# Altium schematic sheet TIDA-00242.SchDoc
size 431 x 279 mm; Date: Not shown in title block; ApprovedBy: Not shown in title block; CheckedBy: Not shown in title block; Author: Not shown in title block; CompanyName: Not shown in title block; Engineer: Not shown in title block; Organization: Not shown in title block; Address1: Not shown in title block; Address2: Not shown in title block; Address3: Not shown in title block; Address4: Not shown in title block; DocumentNumber: 1; Revision: Use project parameter SCH_Rev; SheetNumber: 2; SheetTotal: 3; PageSetup: Record=PageOptions|CenterHorizontal=True|CenterVertical=True|PrintScale=0.64|XCorrection=1.00|YCorrection=1.00|PrintKind=0|BorderSize=5000000|LeftOffset=0|BottomOffset=0|Orientation=2|PaperLength=1000|PaperWidth=1000|Scale=100|PaperSource=15|PrintQuality=600|MediaType=1|DitherType=10|PaperKind=Letter|PrintScaleMode=1
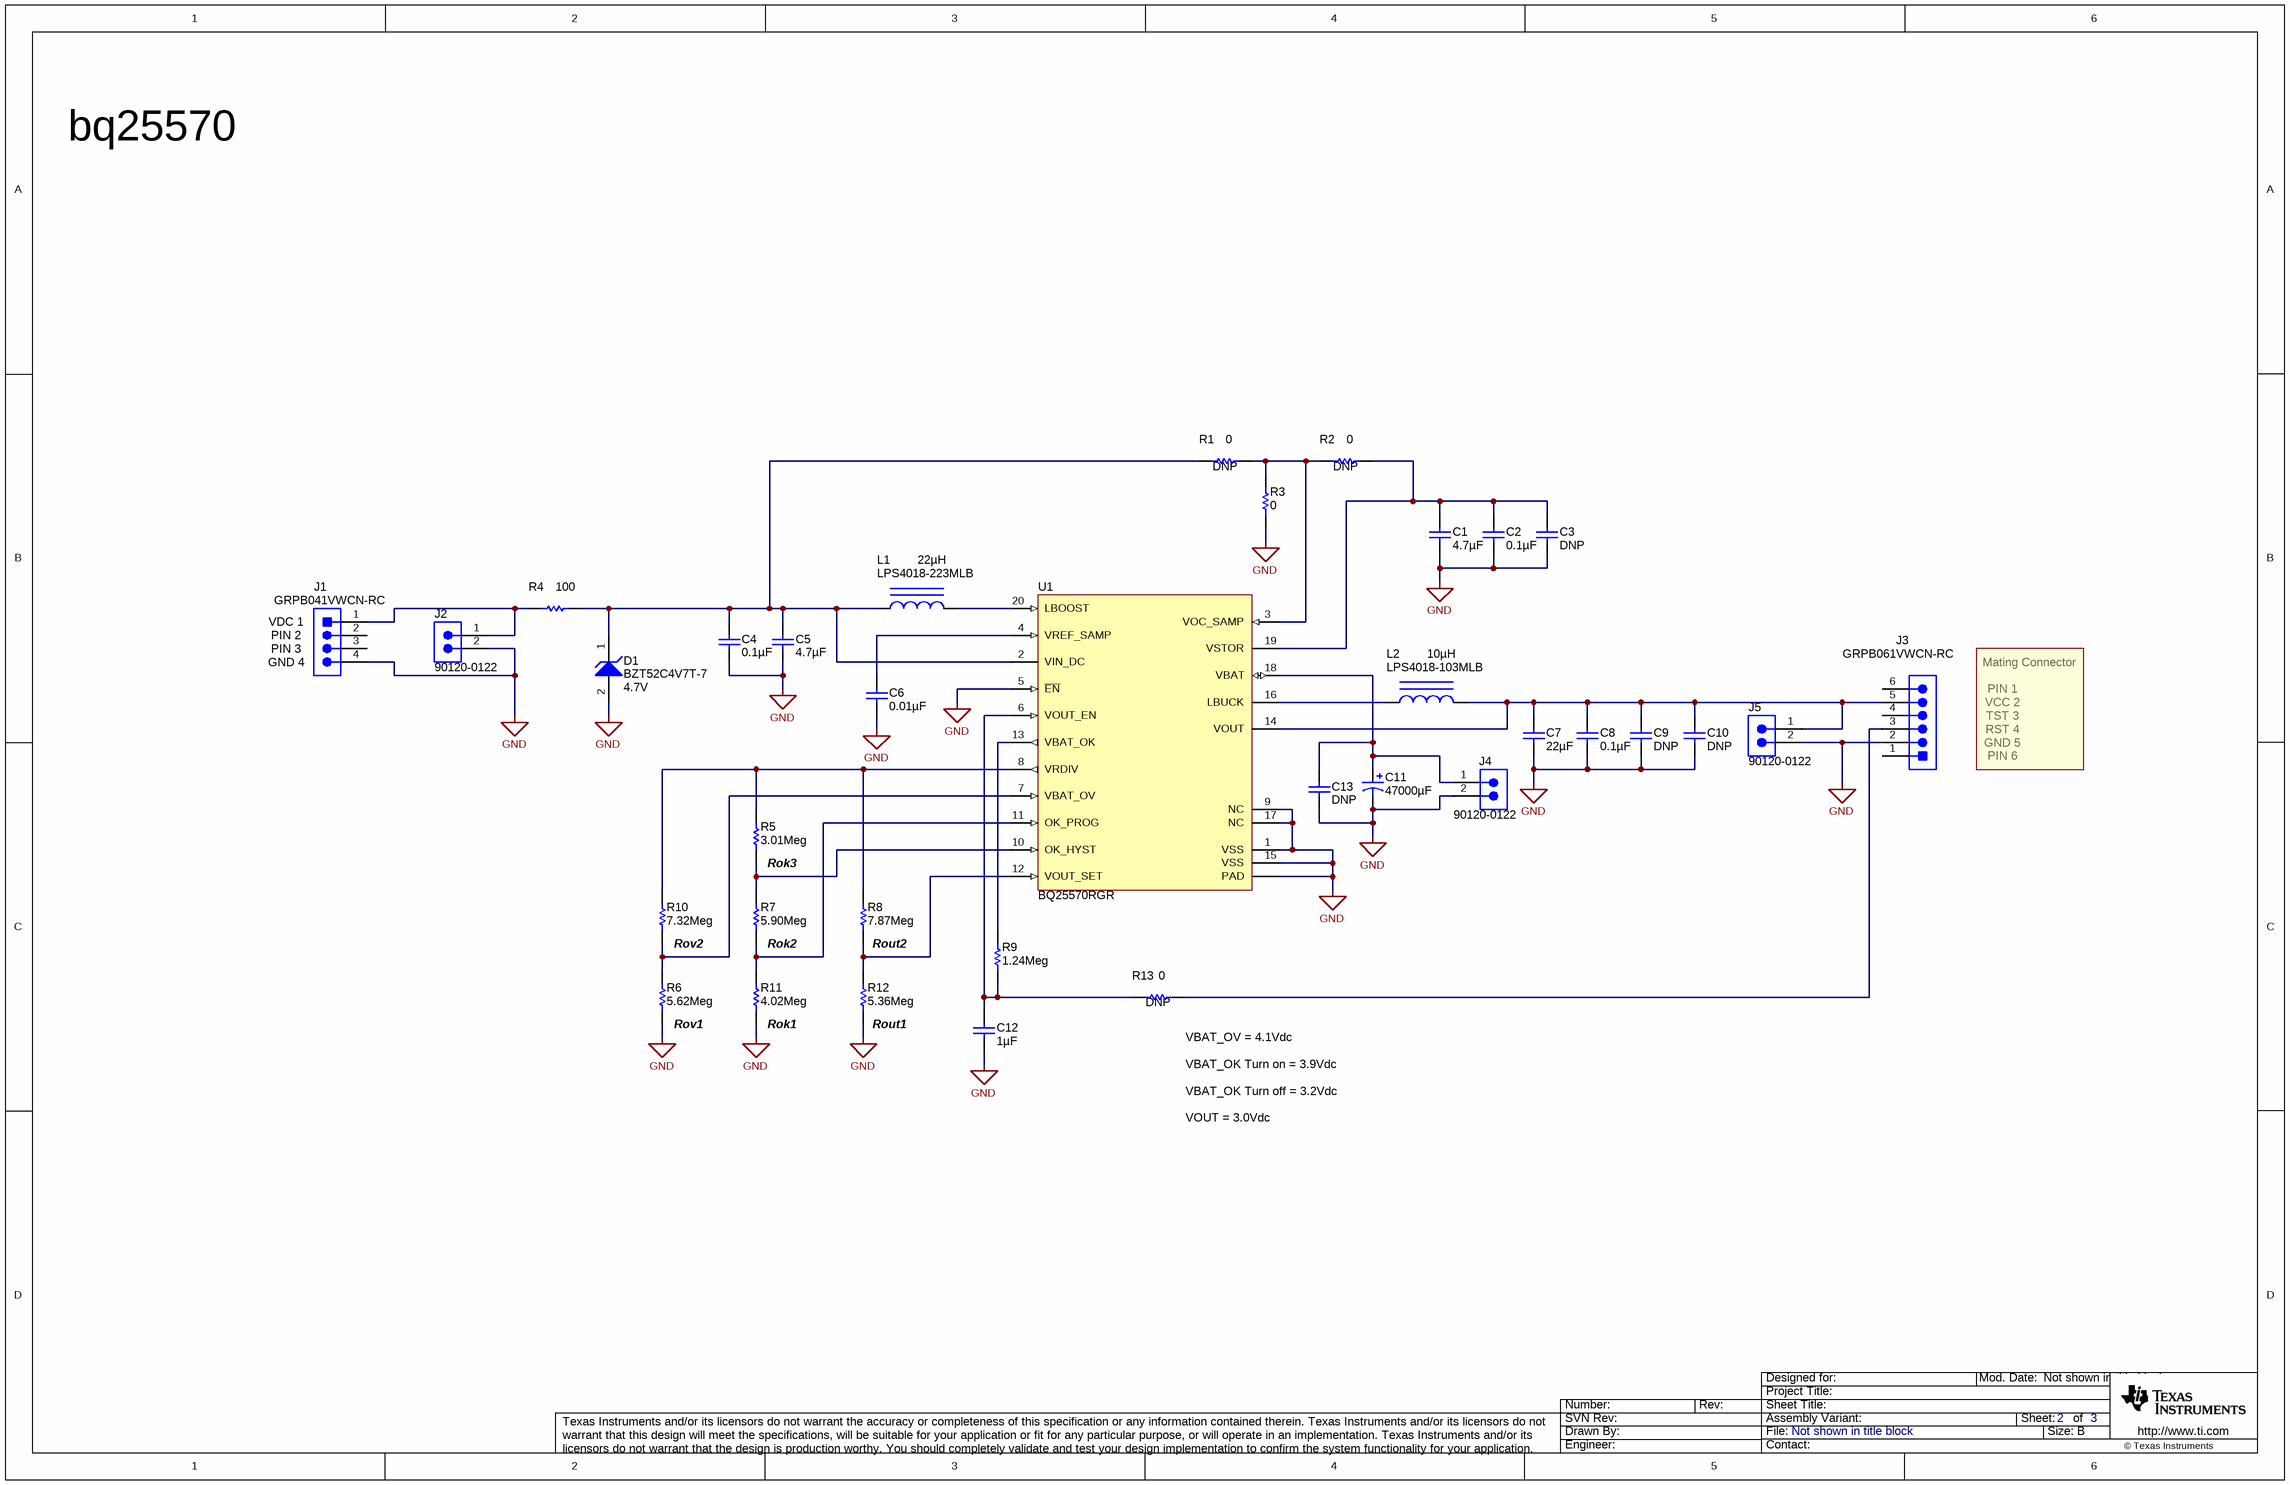
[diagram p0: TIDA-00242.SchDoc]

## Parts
C1  ValueDisplayed: 4.7µF  [0402]  (hidden comment: C1005X5R0J475M050BC)
C2  ValueDisplayed: 0.1µF  [0402]  (hidden comment: GRM155R71A104KA01D)
C3  ValueDisplayed: DNP  [1210]  (hidden comment: C1210C107M9PACTU)
C4  ValueDisplayed: 0.1µF  [0402]  (hidden comment: GRM155R71A104KA01D)
C5  ValueDisplayed: 4.7µF  [0402]  (hidden comment: C1005X5R0J475M050BC)
C6  ValueDisplayed: 0.01µF  [0402]  (hidden comment: GRM155R61A103KA01D)
C7  ValueDisplayed: 22µF  [0603]  (hidden comment: CL10A226MP8NUNE)
C8  ValueDisplayed: 0.1µF  [0402]  (hidden comment: GRM155R71A104KA01D)
C9  ValueDisplayed: DNP  [1210]  (hidden comment: C1210C107M9PACTU)
C10  ValueDisplayed: DNP  [1210]  (hidden comment: C1210C107M9PACTU)
C11  ValueDisplayed: 47000µF  [DX-H_1150x500]  (hidden comment: DX-5R5H473U)
C12  ValueDisplayed: 1µF  [0402]  (hidden comment: C1005X5R0J105M)
C13  ValueDisplayed: DNP  [1210]  (hidden comment: C1210C107M9PACTU)
D1  BZT52C4V7T-7  value 4.7V  [SOD-523]
J1  GRPB041VWCN-RC  [Sullins_GRPB041VWCN]
J2  90120-0122  [CONN_90120-0122]
J3  GRPB061VWCN-RC  [Sullins_GRPB061VWCN]
J4  90120-0122  [CONN_90120-0122]
J5  90120-0122  [CONN_90120-0122]
L1  LPS4018-223MLB  ValueDisplayed: 22µH  [LPS4018]
L2  LPS4018-103MLB  ValueDisplayed: 10µH  [LPS4018]
R1  value 0  Res_ohm: DNP  [0603]  (hidden comment: ERJ-3GEY0R00V)
R2  value 0  Res_ohm: DNP  [0603]  (hidden comment: ERJ-3GEY0R00V)
R3  value 0  [0603]  (hidden comment: ERJ-3GEY0R00V)
R4  value 100  [0402]  (hidden comment: CRCW0402100RJNED)
R5  value 3.01Meg  [0603]  (hidden comment: CRCW06033M01FKEA)
R6  value 5.62Meg  [0603]  (hidden comment: CRCW06035M62FKEA)
R7  value 5.90Meg  [0603]  (hidden comment: CRCW06035M90FKEA)
R8  value 7.87Meg  [0603]  (hidden comment: CRCW06037M87FKEA)
R9  value 1.24Meg  [0603]  (hidden comment: CRCW06031M24FKEA)
R10  value 7.32Meg  [0603]  (hidden comment: CRCW06037M32FKEA)
R11  value 4.02Meg  [0603]  (hidden comment: CRCW06034M02FKEA)
R12  value 5.36Meg  [0603]  (hidden comment: CRCW06035M36FKEA)
R13  value 0  Res_ohm: DNP  [0603]  (hidden comment: ERJ-3GEY0R00V)
U1  BQ25570RGR  [RGR0020A]

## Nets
GND: C1.2 C2.2 C3.2 C4.2 C5.2 C6.2 C7.2 C8.2 C9.2 C10.2 C11.2(-) C12.2 C13.2 D1.2(A) J1.4 J2.2 J3.2 J4.2 J5.2 R3.1 R6.1 R11.1 R12.1 U1.1(VSS) U1.5(~{EN}) U1.9(NC) U1.15(VSS) U1.17(NC) U1.21(PAD)
NetC1_1: C1.1 C2.1 C3.1 R2.2 U1.19(VSTOR)
NetC4_1: C4.1 C5.1 D1.1(K) L1.1 R1.1 R4.2 U1.2(VIN_DC)
NetC6_1: C6.1 U1.4(VREF_SAMP)
NetC7_1: C7.1 C8.1 C9.1 C10.1 J3.5 J5.1 L2.2 U1.14(VOUT)
NetC11_1: C11.1(+) C13.1 J4.1 U1.18(VBAT)
NetC12_1: C12.1 R9.1 R13.1 U1.6(VOUT_EN)
NetJ1_1: J1.1 J2.1 R4.1
NetJ3_3: J3.3 R13.2
NetL1_2: L1.2 U1.20(LBOOST)
NetL2_1: L2.1 U1.16(LBUCK)
NetR1_2: R1.2 R2.1 R3.2 U1.3(VOC_SAMP)
NetR5_1: R5.1 R7.2 U1.10(OK_HYST)
NetR5_2: R5.2 R8.2 R10.2 U1.8(VRDIV)
NetR6_2: R6.2 R10.1 U1.7(VBAT_OV)
NetR7_1: R7.1 R11.2 U1.11(OK_PROG)
NetR8_1: R8.1 R12.2 U1.12(VOUT_SET)
NetR9_2: R9.2 U1.13(VBAT_OK)

Not connected (* = marked no-connect by the designer): J1 2 3; J3 1 4 6

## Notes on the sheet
- bq25570
- (near J1) VDC 1
- (near J1) PIN 2
- (near J1) PIN 3
- (near J1) GND 4
- PIN 1
- VCC 2
- Mating Connector
- TST 3
- RST 4
- GND 5
- PIN 6
- (near R5) Rok3
- (near R10) Rov2
- (near R7) Rok2
- (near R8) Rout2
- (near R6) Rov1
- (near R11) Rok1
- (near R12) Rout1
- (near R13) VBAT_OV = 4.1Vdc
- VBAT_OK Turn on = 3.9Vdc
- VBAT_OK Turn off = 3.2Vdc
- VOUT = 3.0Vdc

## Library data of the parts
C1 C5 = C1005X5R0J475M050BC: CAP, CERM, 4.7uF, 6.3V, +/-20%, X5R, 0402; Manufacturer: TDK; Polarized: N; CompType: Capacitor; U/M: EA; Cap_F: 0.0000047; Tolerance_%: 20; Value1: Unknown; VDC_V: 6.3; TaMin_C: -55; TaMax_C: 85
C2 C4 C8 = GRM155R71A104KA01D: CAP, CERM, 0.1uF, 10V, +/-10%, X7R, 0402; Manufacturer: MuRata; Polarized: N; CompType: Capacitor; U/M: EA; Cap_F: 0.0000001; Tolerance_%: 10; Value1: Unknown; TaMin_C: -55; TaMax_C: 125
C3 C9 C10 C13 = C1210C107M9PACTU: CAP, CERM, 100uF, 6.3V, +/-20%, X5R, 1210; Manufacturer: Kemet; Polarized: N; CompType: Capacitor; U/M: EA; Cap_F: 0.0001; Tolerance_%: 20; Value1: Unknown; VDC_V: 6.3; TaMin_C: -55; TaMax_C: 85
C6 = GRM155R61A103KA01D: CAP, CERM, 0.01uF, 10V, +/-10%, X5R, 0402; Manufacturer: MuRata; Polarized: N; CompType: Capacitor; U/M: EA; Cap_F: 0.00000001; Tolerance_%: 10; Value1: Unknown; TaMin_C: -55; TaMax_C: 85
C7 = CL10A226MP8NUNE: CAP, CERM, 22uF, 10V, +/-20%, X5R, 0603; Manufacturer: Samsung; Polarized: N; CompType: Capacitor; U/M: EA; Cap_F: 0.000022; Tolerance_%: 20; Value1: Unknown; VDC_V: 10; TaMin_C: -55; TaMax_C: 85
C11 = DX-5R5H473U: CAP, Electric Double Layer, 47000uF, 5.5V, +80/-20%, TH; Manufacturer: Elna; Polarized: Y; CompType: Capacitor; U/M: EA; Cap_F: 0.047; Tolerance_%: 80; Value1: Unknown; VDC_V: 5.5; TaMin_C: -25; TaMax_C: 70
C12 = C1005X5R0J105M: CAP, CERM, 1uF, 6.3V, +/-20%, X5R, 0402; Manufacturer: TDK; Polarized: N; CompType: Capacitor; U/M: EA; Cap_F: 0.000001; Tolerance_%: 20; ESR_Ohm: 0.0079; Value1: 0.0079 ohm; VDC_V: 6.3; TaMin_C: -55; TaMax_C: 85
D1 = BZT52C4V7T-7: Diode, Zener, 4.7V, 300mW, SOD-523; Manufacturer: Diodes Inc.; U/M: EA; Power_W: 0.3; Vz_V: 4.7; Value1: 0.3W; RJA_CperW: 417
J1 = GRPB041VWCN-RC: Header, 50mil, 4x1, R/A, TH; Manufacturer: Sullins Connector Solutions; SymbolCreator: a0412235; U/M: EA
J2 J4 J5 = 90120-0122: Header, 100mil, 2x1, Tin plated, TH; Manufacturer: Molex; SymbolCreator: a0412235; U/M: EA
J3 = GRPB061VWCN-RC: Header, 50mil, 6x1, R/A, TH; Manufacturer: Sullins Connector Solutions; SymbolCreator: a0412235; U/M: EA
L1 = LPS4018-223MLB: Inductor, Shielded Drum Core, Ferrite, 22uH, 0.83A, 0.36 ohm, SMD; Manufacturer: Coilcraft; Ind_H: 22.0E-6; Imax_A: 0.83; Irms: 0.9A @ 40C rise; Isat: 0.83A @ 30% inductance drop; DCR_ohm: 0.36; U/M: EA
L2 = LPS4018-103MLB: Inductor, Shielded Drum Core, Ferrite, 10uH, 1.25A, 0.2 ohm, SMD; Manufacturer: Coilcraft; Ind_H: 10.0E-6; Imax_A: 1.25; Irms: 1.25A @ 40C rise; Isat: 1.3A @ 30% inductance drop; DCR_ohm: 0.2; Value1: 0.2 ohm; U/M: EA
R1-R3 R13 = ERJ-3GEY0R00V: RES, 0 ohm, 5%, 0.1W, 0603; Manufacturer: Panasonic; CompType: Resistor; Value_Code: 0000; Tolerance_%: 5; Power_W: 0.1; VDC_V: 50; TempCo: 600 ppm/C; EIA_Code: E24; U/M: EA
R4 = CRCW0402100RJNED: RES, 100 ohm, 5%, 0.063W, 0402; Manufacturer: Vishay-Dale; CompType: Resistor; Value_Code: 100R; Tolerance_%: 5; Power_W: 0.063; VDC_V: 50; TempCo: 200 ppm/C; EIA_Code: E24; U/M: EA
R5 = CRCW06033M01FKEA: RES, 3.01Meg ohm, 1%, 0.1W, 0603; Manufacturer: Vishay-Dale; CompType: Resistor; Res_ohm: 3010000; Value_Code: 3M01; Tolerance_%: 1; Power_W: 0.1; VDC_V: 75; TempCo: 100 ppm/C; EIA_Code: E96; U/M: EA
R6 = CRCW06035M62FKEA: RES, 5.62Meg ohm, 1%, 0.1W, 0603; Manufacturer: Vishay-Dale; CompType: Resistor; Res_ohm: 5620000; Value_Code: 5M62; Tolerance_%: 1; Power_W: 0.1; VDC_V: 75; TempCo: 100 ppm/C; EIA_Code: E96; U/M: EA
R7 = CRCW06035M90FKEA: RES, 5.90Meg ohm, 1%, 0.1W, 0603; Manufacturer: Vishay-Dale; CompType: Resistor; Res_ohm: 5900000; Value_Code: 5M90; Tolerance_%: 1; Power_W: 0.1; VDC_V: 75; TempCo: 100 ppm/C; EIA_Code: E96; U/M: EA
R8 = CRCW06037M87FKEA: RES, 7.87Meg ohm, 1%, 0.1W, 0603; Manufacturer: Vishay-Dale; CompType: Resistor; Res_ohm: 7870000; Value_Code: 7M87; Tolerance_%: 1; Power_W: 0.1; VDC_V: 75; TempCo: 100 ppm/C; EIA_Code: E96; U/M: EA
R9 = CRCW06031M24FKEA: RES, 1.24Meg ohm, 1%, 0.1W, 0603; Manufacturer: Vishay-Dale; CompType: Resistor; Res_ohm: 1240000; Value_Code: 1M24; Tolerance_%: 1; Power_W: 0.1; VDC_V: 75; TempCo: 100 ppm/C; EIA_Code: E96; U/M: EA
R10 = CRCW06037M32FKEA: RES, 7.32Meg ohm, 1%, 0.1W, 0603; Manufacturer: Vishay-Dale; CompType: Resistor; Res_ohm: 7320000; Value_Code: 7M32; Tolerance_%: 1; Power_W: 0.1; VDC_V: 75; TempCo: 100 ppm/C; EIA_Code: E96; U/M: EA
R11 = CRCW06034M02FKEA: RES, 4.02Meg ohm, 1%, 0.1W, 0603; Manufacturer: Vishay-Dale; CompType: Resistor; Res_ohm: 4020000; Value_Code: 4M02; Tolerance_%: 1; Power_W: 0.1; VDC_V: 75; TempCo: 100 ppm/C; EIA_Code: E96; U/M: EA
R12 = CRCW06035M36FKEA: RES, 5.36Meg ohm, 1%, 0.1W, 0603; Manufacturer: Vishay-Dale; CompType: Resistor; Res_ohm: 5360000; Value_Code: 5M36; Tolerance_%: 1; Power_W: 0.1; VDC_V: 75; TempCo: 100 ppm/C; EIA_Code: E96; U/M: EA
U1 = BQ25570RGR: Ultra Low Power Harvester Power Management IC with Boost Charger, and Nano-Powered Buck Converter, RGR0020A; Alternate Manufacturer: None; Manufacturer: Texas Instruments; SymbolCreator: a0412235; U/M: EA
